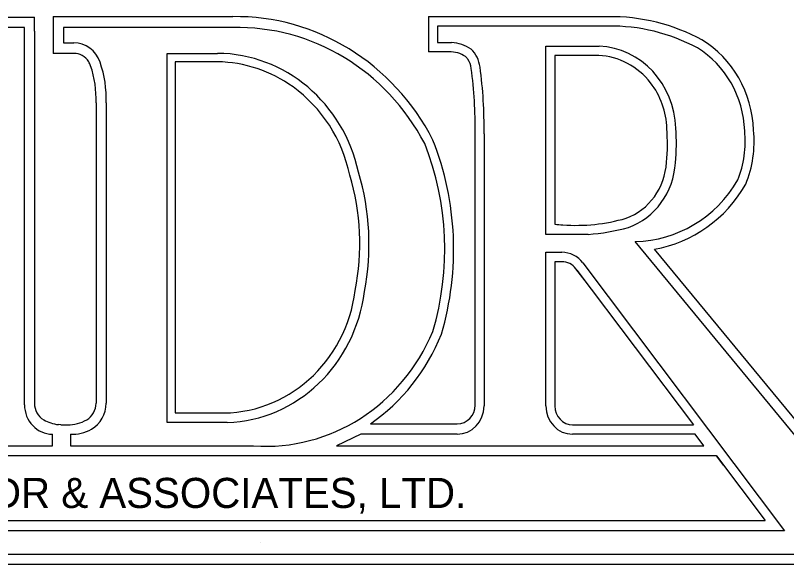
# Model space of a CAD drawing. Extents: x 0 to 34, y 0 to 22.
# Drawn here: x 32.49 to 33.31, y 3.477 to 4.06 of the extents above; entities that cross this region are included whole.
import ezdxf

# ---------------------------------------------------------------- set-up
doc = ezdxf.new("R2010")
doc.units = 0
doc.layers.add('SH_Data', color=7, linetype='Continuous')

msp = doc.modelspace()

# ---------------------------------------------------------------- linework, layer by layer
at = {"layer": 'SH_Data'}
for p, q in [((32.43408, 4.05843), (32.51008, 4.05843)), ((32.51008, 4.04345), (32.51008, 4.05843)), ((32.52996, 4.059), (32.52996, 4.02001)), ((32.52996, 4.059), (32.72096, 4.059)), ((32.92896, 4.059), (32.92896, 4.02146)), ((32.92896, 4.059), (33.11996, 4.059)), ((32.92896, 4.059), (32.92896, 4.02146)), ((32.92896, 4.059), (33.11996, 4.059)), ((32.51008, 4.04345), (32.51008, 3.64811)), ((32.54419, 4.02001), (32.52996, 4.02001)), ((32.55198, 4.02001), (32.54419, 4.02001)), ((32.94319, 4.02146), (32.92896, 4.02146)), ((32.94319, 4.02146), (32.92896, 4.02146)), ((32.95098, 4.02146), (32.94319, 4.02146)), ((32.70486, 4.01101), (32.65976, 4.01101)), ((32.65976, 4.01101), (32.65976, 3.63792)), ((32.57566, 3.96729), (32.57566, 3.64811)), ((32.97852, 3.64621), (32.97852, 3.93474)), ((33.38489, 3.55057), (33.16923, 3.81191)), ((33.08681, 3.78957), (33.2106, 3.62519)), ((32.65976, 3.63792), (32.66831, 3.63792)), ((32.66831, 3.63792), (32.70486, 3.63792)), ((32.53838, 3.62516), (32.53558, 3.62542)), ((32.53838, 3.62516), (32.53558, 3.62542)), ((32.53838, 3.62516), (32.54534, 3.62516)), ((32.86732, 3.62621), (32.95952, 3.62621)), ((33.08223, 3.62519), (33.2106, 3.62519)), ((33.23507, 3.59224), (33.28673, 3.52336)), ((32.21118, 3.52336), (33.28673, 3.52336)), ((32.75, 3.5), (32.75, 3.5)), ((33.44039, 3.47664), (32.07007, 3.47664))]:
    msp.add_line(p, q, dxfattribs=at)
for points in [[(32.49963, 3.64634), (32.49963, 4.04743), (32.43976, 4.04743), (32.13412, 3.55203)], [(32.72096, 4.04743), (32.54097, 4.04743), (32.54097, 4.03132), (32.55198, 4.03132)], [(33.11996, 4.049), (32.93846, 4.049), (32.93846, 4.03146), (32.95356, 4.03146)], [(33.05373, 4.02776), (33.11024, 4.02776)], [(33.09871, 3.82764), (33.05373, 3.82764), (33.05373, 4.02776)], [(32.65139, 3.62757), (32.65139, 4.02001), (32.70486, 4.02001)], [(33.11001, 4.01776), (33.06323, 4.01776), (33.06323, 3.83841)], [(32.58641, 3.96729), (32.58641, 3.96683), (32.58641, 3.64811)], [(32.98802, 3.93464), (32.98802, 3.64519)], [(33.37719, 3.54313), (33.14872, 3.82)], [(33.05373, 3.64519), (33.05373, 3.80857), (33.07085, 3.80857)], [(33.09319, 3.79721), (33.30749, 3.51264), (32.20382, 3.51264)], [(33.07085, 3.79857), (33.06323, 3.79857), (33.06323, 3.64519)], [(33.09537, 3.77821), (33.08574, 3.791)], [(32.71502, 3.62757), (32.65139, 3.62757)], [(32.86732, 3.62621), (32.88937, 3.62621)], [(33.08223, 3.62519), (33.08603, 3.62519)], [(32.41176, 3.61524), (32.2551, 3.61524), (32.24762, 3.60274), (32.5292, 3.60274), (32.5292, 3.61524)], [(32.54836, 3.61524), (32.54836, 3.60274), (32.74315, 3.60274)], [(32.95952, 3.61519), (32.85698, 3.61519), (32.83108, 3.60274), (33.22168, 3.60274), (33.21235, 3.61519), (33.08223, 3.61519)], [(33.24257, 3.58224), (33.23507, 3.59224), (32.24118, 3.59224), (32.20224, 3.52719)], [(32.06602, 3.50059), (32.06602, 3.48764), (33.42994, 3.48764), (33.42994, 3.50061)]]:
    msp.add_lwpolyline(points, dxfattribs=at)
for centre, major_axis, start_param, end_param in [((32.72433, 3.80818), (0, 0.25085), 5.209873, 6.297313), ((33.12226, 3.8329), (0, 0.22611), 5.810103, 6.294452), ((33.12226, 3.8329), (0, 0.22611), 5.810103, 6.294452), ((32.72602, 3.80812), (0, 0.23937), 5.218006, 6.305445), ((33.12243, 3.83351), (0, 0.21551), 5.814829, 6.29527), ((33.16379, 3.93362), (0, 0.11672), 4.753214, 5.755325), ((33.16379, 3.93362), (0, 0.11672), 4.753214, 5.755325), ((32.55198, 4.00001), (0, 0.03131), 5.060756, 6.283185), ((32.95218, 3.98966), (0, 0.04182), 5.696071, 6.248499), ((33.10631, 3.93781), (0, 0.09005), 4.740194, 6.23721), ((33.16379, 3.93362), (0, 0.10672), 4.750292, 5.755325), ((32.55198, 4.00001), (0, 0.02), 5.294753, 6.283185), ((32.70388, 3.8572), (0, 0.16282), 4.938334, 6.276888), ((32.95218, 3.98966), (0, 0.03182), 5.717883, 6.322951), ((32.95511, 4.00164), (0, 0.02041), 5.34604, 5.529903), ((32.95511, 4.00164), (0, 0.03041), 4.832872, 5.561833), ((33.10631, 3.93781), (0, 0.08005), 5.402738, 6.234422), ((32.55198, 4.00001), (0, 0.02), 5.060756, 5.294753), ((32.47755, 3.97156), (0, 0.11467), 4.675194, 5.060756), ((32.70276, 3.85737), (0, 0.15366), 5.684676, 6.268828), ((32.95511, 4.00164), (0, 0.02041), 4.827568, 5.34604), ((32.95511, 4.00164), (0, 0.02041), 4.827568, 5.34604), ((32.47755, 3.97156), (0, 0.10336), 4.671123, 5.060756), ((32.57484, 3.94271), (0, 0.425), 4.693619, 4.857063), ((32.57484, 3.94271), (0, 0.425), 4.693619, 4.857063), ((32.57484, 3.94271), (0, 0.435), 4.693836, 4.856756), ((32.70276, 3.85737), (0, 0.15366), 4.930275, 5.684676), ((33.10631, 3.93781), (0, 0.08005), 4.740194, 5.402738), ((33.10631, 3.93781), (0, 0.08005), 4.740194, 5.402738), ((33.00347, 3.92393), (0, 0.18895), 4.608112, 4.797709), ((33.00347, 3.92393), (0, 0.18895), 4.608112, 4.797709), ((33.00861, 3.92385), (0, 0.19356), 4.607961, 4.797558), ((33.16601, 3.92655), (0, 0.10489), 4.309756, 4.818512), ((33.16601, 3.92655), (0, 0.11489), 4.303317, 4.815541), ((33.16601, 3.92655), (0, 0.11489), 4.303317, 4.815541), ((32.66751, 3.81165), (0, 0.3034), 4.410917, 5.105556), ((32.66751, 3.81165), (0, 0.2934), 4.410917, 5.105556), ((33.11824, 3.90826), (0, -0.06723), 0.330696, 1.511334), ((33.11824, 3.90826), (0, -0.06723), 0.330696, 1.511334), ((33.11779, 3.90865), (0, -0.07773), 0.32607, 1.506707), ((32.62601, 3.8177), (0, 0.25236), 4.509144, 5.018206), ((32.62458, 3.81762), (0, 0.24352), 4.507644, 5.016706), ((33.14666, 3.95705), (0, -0.13706), 0.015856, 1.021186), ((33.14666, 3.95705), (0, -0.14706), 0.16231, 1.026165), ((33.14666, 3.95705), (0, -0.14706), 0.16231, 1.026165), ((33.08509, 4.05603), (0, -0.21884), 6.219099, 6.545404), ((33.08509, 4.05603), (0, -0.21884), 6.219099, 6.545404), ((33.08509, 4.05603), (0, -0.21884), 6.177822, 6.219099), ((33.08509, 4.05603), (0, -0.22884), 0.06267, 0.262218), ((33.07085, 3.77857), (0, 0.03), 5.382662, 6.283185), ((33.07085, 3.77857), (0, 0.02), 5.382662, 6.283185), ((32.70994, 3.78768), (0, -0.14986), 6.247489, 7.723), ((32.70994, 3.78768), (0, -0.16019), 0.033392, 1.439815), ((32.75571, 3.80698), (0, -0.20467), 6.218561, 7.439351), ((32.75561, 3.80484), (0, -0.21386), 0.582172, 1.170799), ((32.52908, 3.64811), (0, -0.02), 4.712389, 5.785309), ((32.55666, 3.64811), (0, -0.02), 0.497877, 1.570796), ((32.55666, 3.64811), (0, -0.03132), 0.497877, 1.570796), ((32.52918, 3.64634), (0, -0.0311), 4.712389, 6.28383), ((32.95952, 3.64621), (0, -0.02), 0, 1.570796), ((32.95952, 3.64519), (0, -0.03), 0, 1.570796), ((33.08223, 3.64519), (0, -0.03), 4.712389, 6.283185), ((33.08223, 3.64519), (0, -0.02), 4.712389, 6.283185), ((32.54013, 3.66951), (0, -0.04436), 5.785308, 6.174936), ((32.54561, 3.66951), (0, -0.04436), 6.276852, 6.781063), ((32.5506, 3.65985), (0, -0.04467), 6.230381, 6.780961)]:
    msp.add_ellipse(centre, major_axis=major_axis, ratio=0.95, start_param=start_param, end_param=end_param, dxfattribs=at)

# ---------------------------------------------------------------- texts
msp.add_text('ADR & ASSOCIATES, LTD.', height=0.0319999, dxfattribs=at).set_placement((32.43646, 3.5368))

doc.saveas('drawing.dxf')
